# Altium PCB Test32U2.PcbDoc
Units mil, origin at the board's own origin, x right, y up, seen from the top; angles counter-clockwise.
Board outline 1450 x 2000 mil, 2 copper layers (Top Layer, Bottom Layer); 26 components, 36 nets, 125 pads, 19 vias.
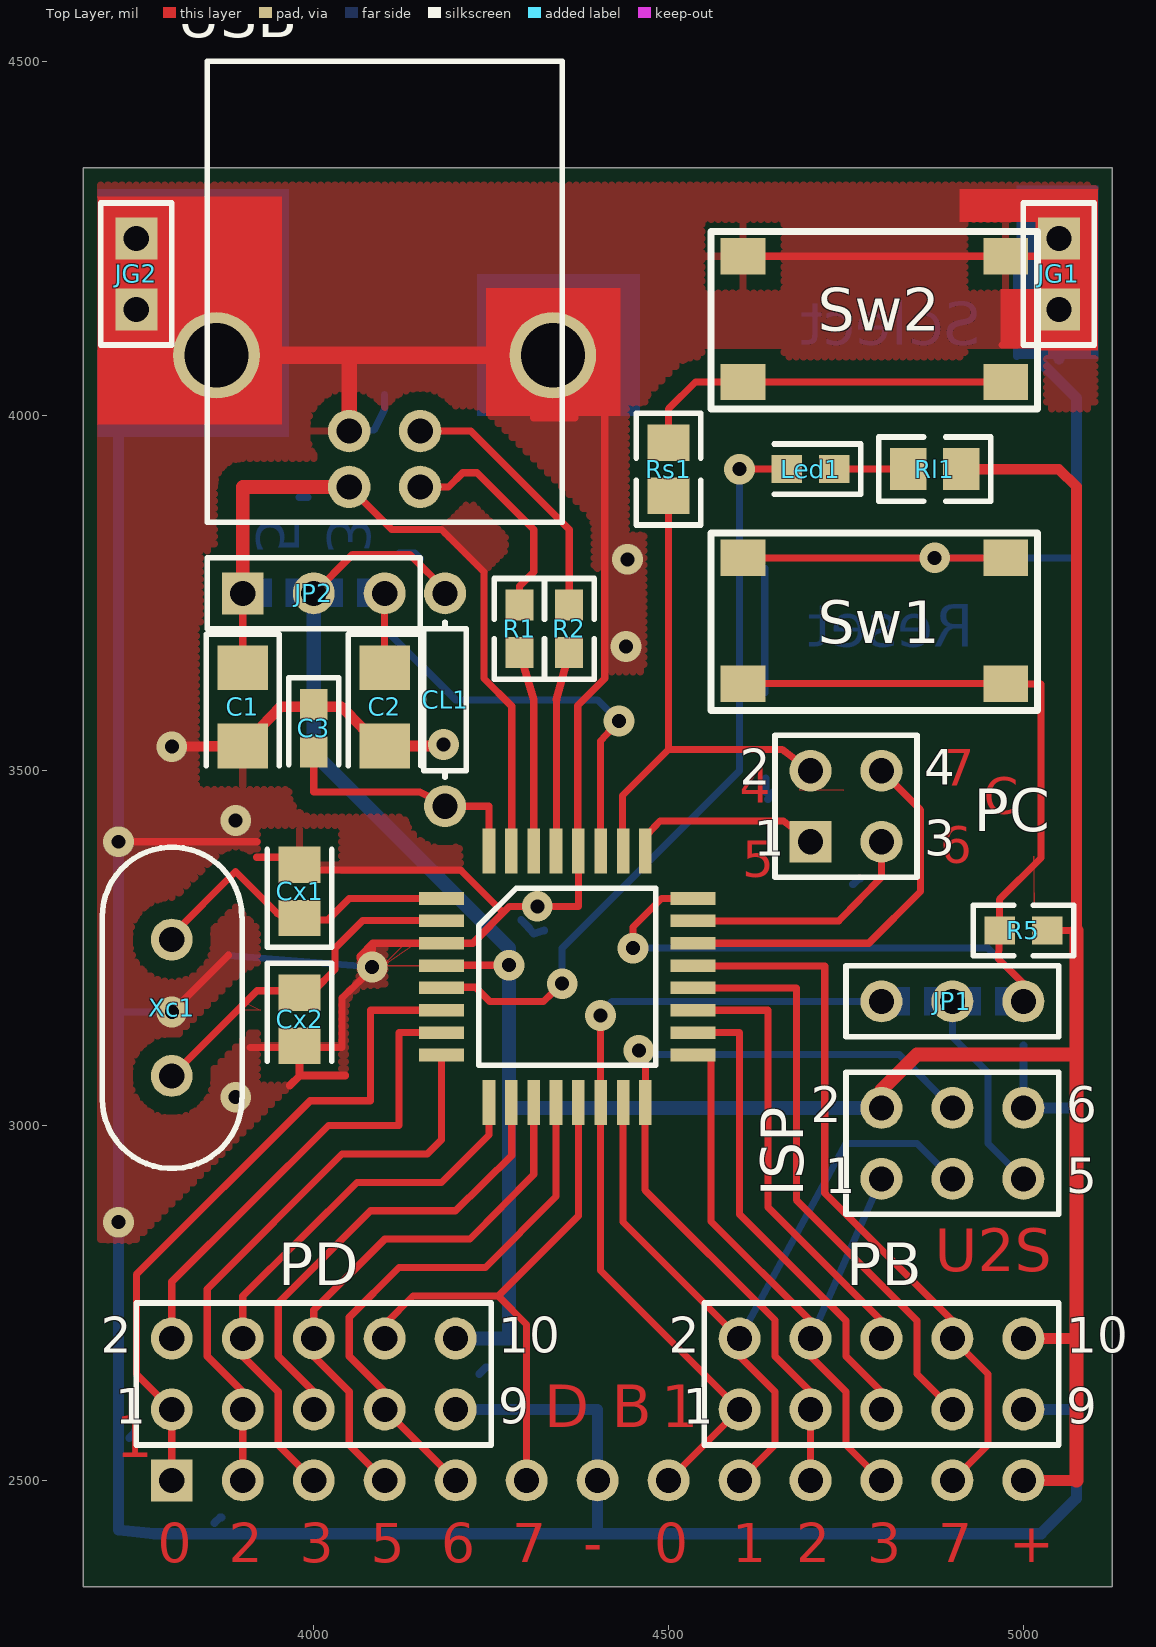
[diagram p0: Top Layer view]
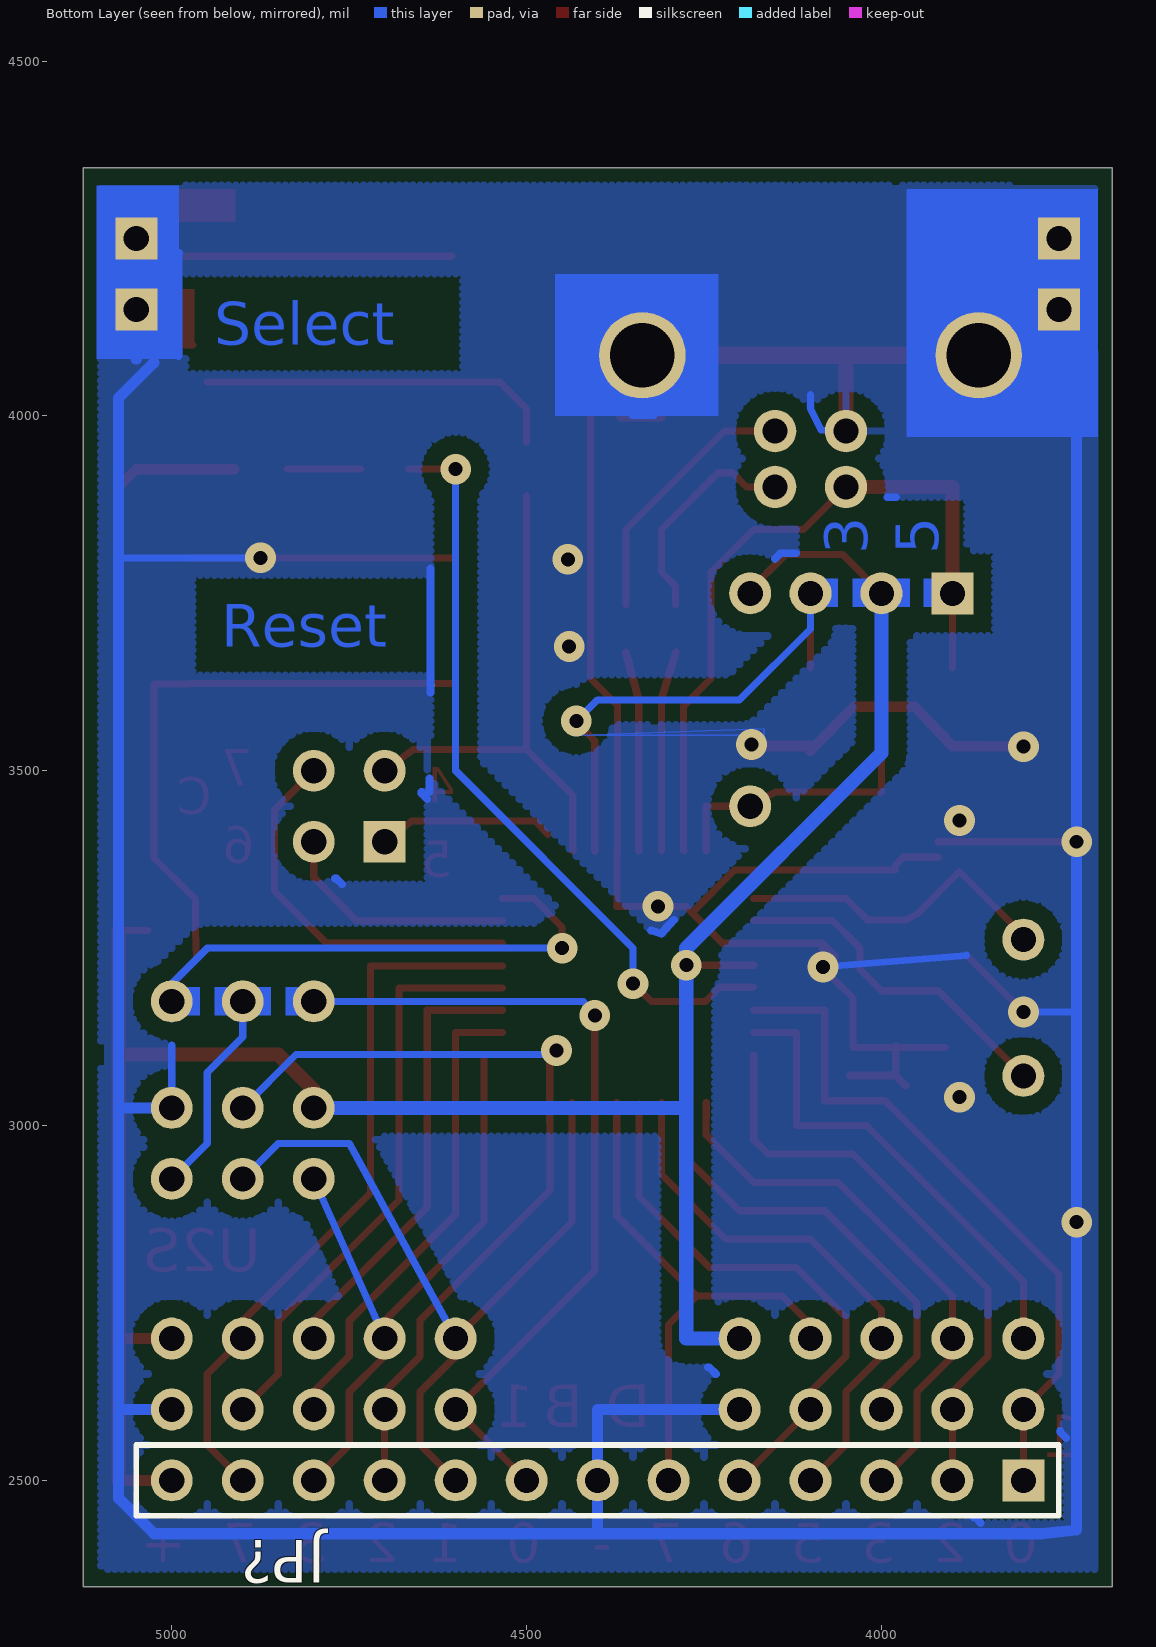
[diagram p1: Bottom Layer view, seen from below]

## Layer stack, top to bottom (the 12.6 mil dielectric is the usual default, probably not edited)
Top Layer: signal copper 1.4
Dielectric: dielectric 12.6, FR-4, Dk 4.8
Bottom Layer: signal copper 1.4

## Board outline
5125,4350 5125,2900 5125,2350 3675,2350 3675,2800 3675,4350

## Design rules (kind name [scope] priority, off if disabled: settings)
Clearance [All] p1: gap=10
ComponentClearance [All] p1: gap=10 collisioncheckmode=0
PolygonConnect [All] p1: connectstyle=Relief reliefconductorwidth=10 reliefentries=4 polygonreliefangle="90 Angle"
RoutingLayers [All] p1: top layer=Horizontal bottom layer=Vertical
RoutingVias [All] p1: holewidth=28 width=50 viastyle="Through Hole" minholewidth=28 minwidth=50 maxholewidth=28 maxwidth=50
SolderMaskExpansion [All] p1: expansion=4
TestPointUsage [All] p1: valid=0 allowmultiple=FALSE
Testpoint [All] p1: side=15 testpointundercomponent=TRUE minsize=40 maxsize=100 preferedsize=60 minholesize=0 maxholesize=40 preferedholesize=32 testpointgrid=1 style=1023 order=1234567890
Width [All] p1: maxlimit=100 minlimit=10 preferedwidth=10 toplayer_prefwidth=11 bottomlayer_prefwidth=11 minimp=50.000000 maximp=50.000000 favimp=50.000000
16 further rules are at their usual default settings.

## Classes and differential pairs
component class Test162: PB U1

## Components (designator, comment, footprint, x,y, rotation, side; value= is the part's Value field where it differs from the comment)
C1 "" CC3216-1206 3900,3590 r270 top
C2 "" CC3216-1206 4100,3590 r270 top
C3 "" CC1608-0603 4000,3560 r270 top
CL1 "Res1" AXIAL-0.3 4185,3600 r90 top
Cx1 "Cap Pol3" CC2012-0805 3980,3330 r90 top
Cx2 "Cap Pol3" CC2012-0805 3980,3150 r270 top
ISP "Header 3X2" HDR2X3 4800,2925 r0 top
JG1 "Header 2" HDR1X2 5050,4250 r270 top
JG2 "Header 2" HDR1X2 3750,4250 r270 top
JP1 "Header 3" HDR1X3#1 4800,3175 r0 top
JP2 "Header 3" HDR1X3#2 3900,3750 r0 top
JP? "Header 13" HDR1X13 3800,2500 r0 bottom
Led1 "" CC1608-0603 4700,3925 r180 top
PB "Header 5X2" HDR2X5 4600,2600 r0 top
PC "Header 2X2" HDR2X2 4700,3400 r0 top
PD "Header 5X2" HDR2X5 3800,2600 r0 top
R1 "Res3" C1608-0603 4290,3700 r270 top
R2 "Res3" C1608-0603 4360,3700 r270 top
R5 "" C1608-0603 5000,3275 r0 top
Rl1 "Res Semi" CR2012-0805 4875,3925 r0 top
Rs1 "Res Semi" CR2012-0805 4500,3925 r90 top
Sw1 "Component_1" MTS-1132 4975,3800 r180 top
Sw2 "Component_1" MTS-1132 4975,4225 r180 top
USB "Component_1" USBB 4050,3900 r0 top
Xc1 "Component_1" HC49 3800,3070 r90 top
? "Mega32U2" ATMega32U2 4180,3320 r0 top

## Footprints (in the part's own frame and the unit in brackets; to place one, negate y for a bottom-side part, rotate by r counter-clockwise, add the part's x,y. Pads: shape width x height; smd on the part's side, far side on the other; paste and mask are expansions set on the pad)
ATMega32U2 [mm]
  rect 1.6x0.45 smd: 1(0,0) 2(0,-0.8) 3(0,-1.6) 4(0,-2.4) 5(0,-3.2) 6(0,-4) 7(0,-4.8) 8(0,-5.6) 17(9,-5.6) 18(9,-4.8) 19(9,-4) 20(9,-3.2) 21(9,-2.4) 22(9,-1.6) 23(9,-0.8) 24(9,0)
  rect 0.45x1.6 smd: 9(1.7,-7.3) 10(2.5,-7.3) 11(3.3,-7.3) 12(4.1,-7.3) 13(4.9,-7.3) 14(5.7,-7.3) 15(6.5,-7.3) 16(7.3,-7.3) 25(7.3,1.7) 26(6.5,1.7) 27(5.7,1.7) 28(4.9,1.7) 29(4.1,1.7) 30(3.3,1.7) 31(2.5,1.7) 32(1.7,1.7)
  silkscreen extent 1.34,-5.96 7.67,0.36
AXIAL-0.3 [mm]
  round 1.5 hole 0.9: 1(-3.81,0) 2(3.81,0)
  silkscreen extent -2.77,-0.76 2.77,0.76
C1608-0603 [mm]
  rect 1.1x1 smd: 1(-0.85,0) 2(0.85,0)
  silkscreen extent -1.8,-0.9 1.8,0.9
CC1608-0603 [mm]
  rect 1.1x1 smd: 1(-0.85,0) 2(0.85,0)
  silkscreen extent -1.8,-0.9 1.3,0.9
CC2012-0805 [mm]
  rect 1.3x1.5 smd: 1(-0.95,0) 2(0.95,0)
  silkscreen extent -2,-1.15 1.5,1.15
CC3216-1206 [mm]
  rect 1.6x1.8 smd: 1(-1.4,0) 2(1.4,0)
  silkscreen extent -2.6,-1.3 2.1,1.3
CR2012-0805 [mm]
  rect 1.3x1.5 smd: 1(-0.95,0) 2(0.95,0)
  silkscreen extent -2,-1.15 2,1.15
HC49 [mm]
  round 1.5 hole 0.9: 1(0,0) 2(4.88,0)
  silkscreen extent -3.31,-2.51 8.19,2.49
HDR1X2 [mm] "Connector; Header; 2 Position"
  rect 1.5x1.5 hole 0.9: 1(0,0) 2(2.54,0)
  silkscreen extent -1.27,-1.27 3.81,1.27
HDR1X3#1 [mm] "Connector; Header; 3 Position"
  round 1.5 hole 0.9: 1(0,0) 2(2.54,0) 3(5.08,0)
  silkscreen extent -1.27,-1.27 6.35,1.27
HDR1X3#2 [mm] "Connector; Header; 3 Position"
  rect 1.5x1.5 hole 0.9: 1(0,0)
  round 1.5 hole 0.9: 2(2.54,0) 3(5.08,0)
  silkscreen extent -1.27,-1.27 6.35,1.27
HDR1X13 [mm] "Connector; Header; 13 Position"
  rect 1.5x1.5 hole 0.9: 1(0,0)
  round 1.5 hole 0.9: 2(2.54,0) 3(5.08,0) 4(7.62,0) 5(10.16,0) 6(12.7,0) 7(15.24,0) 8(17.78,0) 9(20.32,0) 10(22.86,0) 11(25.4,0) 12(27.94,0) 13(30.48,0)
  silkscreen extent -1.27,-1.27 31.75,1.27
HDR2X2 [mm] "Connector; Header; 2x2 Position"
  rect 1.5x1.5 hole 0.9: 1(0,0)
  round 1.5 hole 0.9: 2(0,2.54) 3(2.54,0) 4(2.54,2.54)
  silkscreen extent -1.27,-1.27 3.81,3.81
HDR2X3 [mm] "Connector; Header; 3x2 Position"
  round 1.5 hole 0.9: 1(0,0) 2(0,2.54) 3(2.54,0) 4(2.54,2.54) 5(5.08,0) 6(5.08,2.54)
  silkscreen extent -1.27,-1.27 6.35,3.81
HDR2X5 [mm] "Connector; Header; 5x2 Position"
  round 1.5 hole 0.9: 1(0,0) 2(0,2.54) 3(2.54,0) 4(2.54,2.54) 5(5.08,0) 6(5.08,2.54) 7(7.62,0) 8(7.62,2.54) 9(10.16,0) 10(10.16,2.54)
  silkscreen extent -1.27,-1.27 11.43,3.81
MTS-1132 [mm]
  rect 1.6x1.3 smd: 1(0,0) 1(9.4,0) 2(0,4.5) 2(9.4,4.5)
  silkscreen extent -1.14,-0.89 10.54,5.46
USBB [mm]
  round 1.52 hole 0.9: 1(0,0) 2(2.54,0) 3(2.54,2) 4(0,2)
  round 3.1 hole 2.3: 5(-4.75,4.71) 5(7.29,4.71)
  silkscreen extent -5.08,-1.27 7.62,15.24

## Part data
C1 C2 C3 Cx1 Cx2: library part "Cap Semi", "Capacitor (Semiconductor SIM Model)"
CL1 R1 R2: "Resistor"
ISP: "Header, 3-Pin, Dual row"
JG1 JG2: "Header, 2-Pin"
JP1 JP2: "Header, 3-Pin"
JP?: library part "Header 12", "Header, 12-Pin"
Led1: library part LED3, "Typical BLUE SiC LED"
PB PD: "Header, 5-Pin, Dual row"
PC: library part "Header 5X2", "Header, 5-Pin, Dual row"
R5: library part Res3, "Resistor"
Rl1 Rs1: "Semiconductor Resistor"
?: library part Component_1

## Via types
v1: diameter 43.31, hole 19.68, Top Layer to Bottom Layer, tented both sides, 19 vias

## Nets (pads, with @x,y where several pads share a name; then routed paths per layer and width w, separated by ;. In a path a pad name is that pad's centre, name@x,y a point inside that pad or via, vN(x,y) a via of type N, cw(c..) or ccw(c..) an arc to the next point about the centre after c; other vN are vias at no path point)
AVCC: ?.32 C3.2 CL1.1 | length 371.3
  Top Layer w10: C3.2 4000,3470 4150,3470 4190,3450 4247,3450 ?.32
D+: ?.29 R2.2 | length 282
  Top Layer w10: ?.29@4342,3386.93 4342,3600
  Top Layer w11: 4342,3600 R2.2
D-: ?.30 R1.2 | length 282.5
  Top Layer w10: ?.30@4310,3386.93 4310,3600
  Top Layer w11: R1.2 4310,3600
GND: ?.3 ?.28 C1.2 C2.2 C3.1 Cx1.2 Cx2.2 ISP.6 JG1.1 JG1.2 JG2.1 JG2.2 JP?.7 PB.9 PD.9 Sw1.1 Sw2.1 USB.4 USB.5 | length 10874.3
  Top Layer w10: v1(3725,3400) 3770,3400 3920,3400 ; v1(3800,3160) 3880,3240 ; 3910,3110 4040,3110 4040,3180 4070,3209 v1(4082.3,3223.5) 4083,3257 ; Cx1.2@3980,3360 4207,3360 4266,3301 ; v1@4065.5,3235.3 4065,3239 4083,3257 ; v1@4180.88,3534.88 v1(4183,3537) ; ?.28@4372,3386.93 4372,3592 4410,3630 4410,4010 ; 4372.91,3309 ?.28 ; 4373,3309 4276,3309 4224,3257 ?.3 4129,3257 4083,3257 ; Sw1.1@4604.92,3800 Sw1.1@4975,3800 ; Sw2.1@4604.92,4225 5054,4225 JG1.1 ; 4969.97,4099.99 5025.97,4099.99
  Top Layer w11: 3919.97,3378.23 3969.17,3378.23 Cx1.2 ; 3966.3,3056.51 3980.3,3070.5 ; Cx2.2 3980,3070.8 3980.3,3070.5 ; 4044.5,3070.5 3980.3,3070.5 ; 4310,3997.99 4367.82,3997.99
  Top Layer w15: v1(3800,3534) C1.2 3953,3590 4039,3590 4096.73,3531.65 C2.2@4100,3528.35 ; C2.2 v1@4180.88,3534.88
  Top Layer w21.38: USB.4 4050,4084.43
  Top Layer w25: USB.5@3862.99,4085.43 USB.5@4337.01,4085.43
  Bottom Layer w10: 3730,3160 v1(3800,3160) ; 3880,3240 v1(4082.3,3223.5) ; USB.4 4085,3980 4100,4010 4100,4030 ; v1(4875,3800) 5075,3800
  Bottom Layer w11: 3739.97,2560.03 3747.98,2568.03 3748.01,2570 ; 3860.03,2439.97 3868.06,2448.01 3870,2448.01 ; 3979.5,3885.49 3991.35,3885.49 ; 4120.48,3806.43 4142.34,3806.43 4150,3798.77 ; 4233.22,2650 4242.72,2659.5 4244.31,2659.5 ; 4303.6,3278.68 4292.4,3289.87 4310,3270.38 4324.9,3275.1 ; 4321,4001 4351,4001 ; 4635.5,3610 4635.5,3785 ; 4637,3470 4637,3489 ; 4639.97,3460 4648.01,3468.03 4648.01,3470 ; 4760,3339.97 4768.03,3348.01 4770,3348.01 ; 4989.97,4230 4990.5,4229.47 4990.5,4084.5 ; ISP.6 5000,3113
  Bottom Layer w15.75: 3750,4050 JG2.2 JG2.1 ; 3775,4075 3725,4025 3725,2475 3725,2430 3775,2425 5025,2425 5075,2475 5075,4025 5025,4075 ; PD.9 4400,2600 4400,2425 ; PB.9 5075,2600 ; ISP.6 5075,3025 ; 5050,4080 JG1.2 JG1.1
  other v1: 3725,2864 3890,3040 4315,3309 3890,3430 4440,3675 4442,3798
NetLed1_1: Led1.1 Rl1.1 | length 104.1
  Top Layer w10: Led1.1 Rl1.1
NetRs1_2: Rs1.2 Sw2.2 | length 513.3
  Top Layer w10: Rs1.2 4500,4010 4537.84,4047.84 Sw2.2@4950,4047.84
PB0: ?.14 JP1.1 JP?.8 PB.1 | length 1183.2
  Top Layer w10: v1(4404,3155) 4404,2796 PB.1 JP?.8
  Bottom Layer w10: v1(4404,3155) 4420,3175 JP1.1
PB1: ?.15 ISP.3 JP?.9 PB.2 | length 1125.9
  Top Layer w10: ?.15@4436,3032.6 4436,2864 PB.2 4600,2675 4650,2625 4650,2550 JP?.9
  Bottom Layer w10: PB.2 4750,2975 4850,2975 ISP.3
PB2: ?.16 ISP.4 JP?.10 PB.3 | length 1154.5
  Top Layer w10: v1(4458,3106) 4467.4,3096.6 4467,2909 4650,2726 ; 4650,2725 4650,2675 PB.3@4700,2625 ; JP?.10 PB.3
  Bottom Layer w10: v1(4458,3106) 4475,3100 4825,3100 ISP.4
PB3: ?.17 ISP.1 JP?.11 PB.4 | length 945.2
  Top Layer w10: ?.17@4560,3100 4560,2865 4700,2725 PB.4 4701,2674 4750,2625 4750,2550 JP?.11
  Bottom Layer w10: PB.4 ISP.1
PB4: ?.18 PB.5 | length 679.5
  Top Layer w10: ?.18 4600,3131 4600,2875 4750,2725 4750,2675 4800,2625 PB.5
PB5: ?.19 PB.6 | length 634.5
  Top Layer w10: ?.19 4640,3162.52 4640,2885 4800,2725 PB.6
PB6: ?.20 PB.7 | length 830.8
  Top Layer w10: ?.20 4680,3194.02 4680,2895 4850,2725 4850,2650 PB.7
PB7: ?.21 JP?.12 PB.8 | length 1026.6
  Top Layer w10: ?.21@4534.33,3225 4720,3225 4720,2905 4900,2725 PB.8 4950,2650 4950,2550 JP?.12
PC1: ?.24 JP1.3 R5.1 Sw1.2 | length 1657.5
  Top Layer w10: v1(4450,3250) 4450,3280 4490,3320 ?.24 ; Sw1.2@4604.92,3622.83 Sw1.2@4975,3622.84 ; Sw1.2@4975,3622 5025,3622 5025,3377 4966.53,3318.86 R5.1 4965,3235 5000,3200 JP1.3
  Bottom Layer w10: v1(4450,3250) 4950,3250 5000,3200 JP1.3 JP1.3@5000,3150
PC2: ?.5 Led1.2 | length 1083.1
  Top Layer w10: ?.5@4180.35,3195 4228,3195 4248,3175 4324,3175 v1(4350,3200) ; v1(4600,3925) Led1.2
  Bottom Layer w10: v1(4350,3200) 4350,3250 4600,3500 v1(4600,3925)
PC4: ?.26 PC.2 Rs1.1 | length 737.6
  Top Layer w10: ?.26@4435,3386.93 4435,3465 4500,3530 ; Rs1.1 4500,3530 ; PC.2 4660,3530 4500,3530
PC5: ?.25 PC.1 | length 248
  Top Layer w10: ?.25@4470,3410 4488,3429 4662,3429 PC.1
PC6: ?.23 PC.3 | length 341.2
  Top Layer w10: ?.23 4740,3288.5 ; 4740,3289 4800,3350 PC.3
PC7: ?.22 PC.4 | length 543.7
  Top Layer w10: ?.22 4782,3257.01 4855,3330 4855,3445 PC.4
PD0: ?.6 JP?.1 PD.1 | length 969.7
  Top Layer w10: JP?.1 PD.1 3750,2650 3750,2790 3995,3035 4080,3035 4080,3162.52 ?.6
PD1: ?.7 PD.2 | length 681.8
  Top Layer w10: PD.2 3800,2780 4021,3000 4120,3000 4120,3131 ?.7
PD2: ?.8 JP?.2 PD.3 | length 827.2
  Top Layer w10: JP?.2 3900,2625 3850,2675 3850,2770 4040,2960 4160,2960 4180,2980 ?.8
PD3: ?.9 JP?.3 PD.4 | length 787.8
  Top Layer w10: JP?.3 3950,2550 3950,2625 3900,2675 PD.4 3900,2760 4061,2920 4180,2920 4247,2987 ?.9
PD4: ?.10 PD.5 | length 660.2
  Top Layer w10: PD.5 4000,2625 3950,2675 3950,2750 4080,2880 4200,2880 4279,2958 ?.10@4279,3032.6
PD5: ?.11 JP?.4 PD.6 | length 772.4
  Top Layer w10: JP?.4 4050,2550 4050,2625 4000,2675 PD.6 4000,2740 4100,2840 4220,2840 4310,2931 ?.11@4310,3032.6
PD6: ?.12 JP?.5 PD.7 | length 782.7
  Top Layer w10: JP?.5 PD.7 4100,2625 4050,2675 4050,2730 4120,2800 4240,2800 ; 4242,2800 4341.5,2900 ?.12@4341.5,3030.5
PD7: ?.13 JP?.6 PD.8 | length 792.5
  Top Layer w10: PD.8 4100,2720 4140,2760 4260,2760 ; JP?.6 4300,2720 4260,2760 ; ?.13@4373,3032.6 4373,2873 4260,2760
PRST: ISP.5 JP1.2 | length 291.4
  Bottom Layer w10: JP1.2 4900,3125 4950,3075 4950,2975 ISP.5
U+: R2.1 USB.3 | length 374
  Top Layer w10: USB.3 4221.26,3978.74 4360,3840 R2.1
U-: R1.1 USB.2 | length 316.2
  Top Layer w10: USB.2 4190,3900 4210,3920 4230,3920 4310,3840 4310,3780 4290,3760 R1.1
UCAP: ?.27 C2.1 JP2.3 | length 732.9
  Top Layer w10: C2.1 JP2.3 ; ?.27@4404,3386 4404,3542 v1(4430,3570)
  Bottom Layer w10: JP2.3 4100,3700 4200,3600 4400,3600 v1(4430,3570)
UVCC: ?.31 C1.1 JP2.1 USB.1 | length 1053.8
  Top Layer w10: C1.1 JP2.1 ; USB.1 4110,3840 4180,3840 4240,3780 4240,3630 4279,3591 ?.31@4279,3386.93
  Top Layer w19.68: JP2.1 3900,3900 USB.1
VCC: ?.4 CL1.2 ISP.2 JP2.2 JP?.13 PB.10 PD.10 R5.2 Rl1.2 | length 4178.3
  Top Layer w10: JP2.2 4055,3805 4135,3805 CL1.2@4189,3751 ; ?.4@4180,3226 v1(4275,3226) ; R5.2 5075,3275
  Top Layer w15: Rl1.2 5050,3925 5075,3900
  Top Layer w15.75: ISP.2 ISP.2@4800,3050 ; JP?.13 5075,2500 ; PB.10 5075,2700 ; 5075,3275 5075,3900
  Top Layer w20: ISP.2@4800,3050 4850,3100 5075,3100 ; 5075,2500 5075,3275
  Bottom Layer w20: JP2.2 4000,3700 4000,3525 4275,3250 v1(4275,3226) 4275,2700 PD.10 ; 4275,3025 ISP.2
XT1: ?.1 Cx1.1 Xc1.2 | length 457.4
  Top Layer w10: Xc1.2@3800,3268 3890,3358 3949,3299 ; 3948,3299 3965,3290 4020,3290 4050,3320 ?.1
XT2: ?.2 Cx2.1 Xc1.1 | length 488.3
  Top Layer w10: Xc1.1 3920,3190 4000,3190 4030,3220 4030,3250 4069,3289 ?.2@4180,3289

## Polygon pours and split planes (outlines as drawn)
GND on Top Layer (hatched 90Degree grid 10 track 11, remove dead copper): 5100,4325 3700,4325 3700,2840 4000,2825 4100,3025 4100,3340 4020,3345 4020,3360 4207,3360 4200,3450 3946,3607 3900,3875 4200,3950 4410.19,3640 4500,3640 4508,4041 5003.06,4070.97 5004,4010 5100,4010 5100,4100
UVCC on Top Layer (hatched 45Degree grid 8 track 10): 4180,3840 4220,3880 4270,3830 4270,3810 4240,3780
no net on Top Layer (none): 3925,3162.52 3900,3162.52 3900,3175
no net on Top Layer (none): 4180,3225.51 4075,3225.51 4075,3225
no net on Top Layer (none): 4746.93,3472.6 4685,3472.6 4685,3474
no net on Top Layer (none): 5014.33,3379.53 5014.33,3312 5016,3312
no net on Top Layer (none): 4096,3224 4130,3258 4145,3258
GND on Bottom Layer (hatched 90Degree grid 10 track 11, remove dead copper): 3700,4325 5100,4325 5100,2375 3700,2375
GND on Bottom Layer (none): 4165,3550 4425,3550 4165,3559
no net on Bottom Layer (none): 4425,3550 4165,3550 4165,3559
no net on Top Solder (hatched 90Degree grid 10 track 11): 4234,2997 4481,2997 4481,3069 4234,3069
no net on Top Solder (hatched 90Degree grid 10 track 11): 4234,3423 4480,3423 4480,3351 4234,3351
no net on Top Solder (hatched 90Degree grid 10 track 11): 4144,3087 4144,3333 4216,3333 4216,3087
no net on Top Solder (hatched 90Degree grid 10 track 11): 4499,3087 4499,3334 4570,3334 4570,3087
no net on Bottom Solder (hatched 90Degree grid 10 track 11): 4921,3195 4980,3195 4980,3154 4923,3154 4923,3158
no net on Bottom Solder (hatched 90Degree grid 10 track 11): 4822,3195 4877,3195 4877,3154 4820,3154 4820,3155
no net on Bottom Solder (hatched 90Degree grid 10 track 11): 4021,3771 4080,3771 4080,3731 4023,3731
no net on Bottom Solder (hatched 90Degree grid 10 track 11): 3928,3771 3979,3771 3979,3731 3930,3731

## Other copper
Top Layer:
  rectangle net GND: 4968,4096 5050,4179
  rectangle net GND: 5017,4092 5105,4273
  rectangle net GND: 4910,4273 5105,4320
  rectangle net GND: 4243,4000 4432,4180
  rectangle net GND: 3695,3988 3955,4309
  text "7" at 4886,3479 h51.18
  text "4" at 4600,3455 h50
  text "C" at 4944,3439 h51.18
  text "6" at 4883,3370 h51.18
  text "5" at 4604,3350 h51.18
  text "U2S" at 4875,2795 h60
  text "D" at 4325,2575 h60
  text "B" at 4420,2575 h60
  text "1" at 4490,2575 h60
  text "1" at 3721,2533 h60
  text "0" at 3780,2385 h55.12
  text "2" at 3880,2385 h55.12
  text "3" at 3980,2385 h55.12
  text "5" at 4080,2385 h55.12
  text "6" at 4180,2385 h55.12
  text "7" at 4280,2385 h55.12
  text "-" at 4380,2385 h55.12
  text "0" at 4480,2385 h55.12
  text "1" at 4590,2385 h55.12
  text "2" at 4680,2385 h55.12
  text "3" at 4780,2385 h55.12
  text "7" at 4880,2385 h55.12
  text "+" at 4980,2385 h55.12
Bottom Layer:
  rectangle net GND: 3695,3970 3965,4320
  rectangle net GND: 4990,4080 5106,4325
  rectangle net GND: 4230,4000 4460,4200
  rectangle net VCC: 4001,3731 4041,3771
  rectangle net VCC: 3960,3731 4000,3771
  rectangle net UVCC: 3901,3731 3941,3771
  region net PC1: 5000,3195 4960,3195 4960,3155 5000,3155
  region net PRST: 4940,3195 4900,3195 4900,3155 4940,3155
  region net PRST: 4900,3195 4860,3195 4860,3155 4900,3155
  region net PB0: 4840,3195 4800,3195 4800,3155 4840,3155
  rectangle net UCAP: 4061,3731 4101,3771
  text "Select" at 4940,4100 h60
  text "5" at 3920,3805 h60 r270
  text "3" at 4020,3805 h60 r270
  text "Reset" at 4930,3675 h60

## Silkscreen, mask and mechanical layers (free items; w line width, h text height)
Mechanical 1:
  lines w10: 3650,2325 5150,2325 5150,4375 3650,4375 3650,2325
